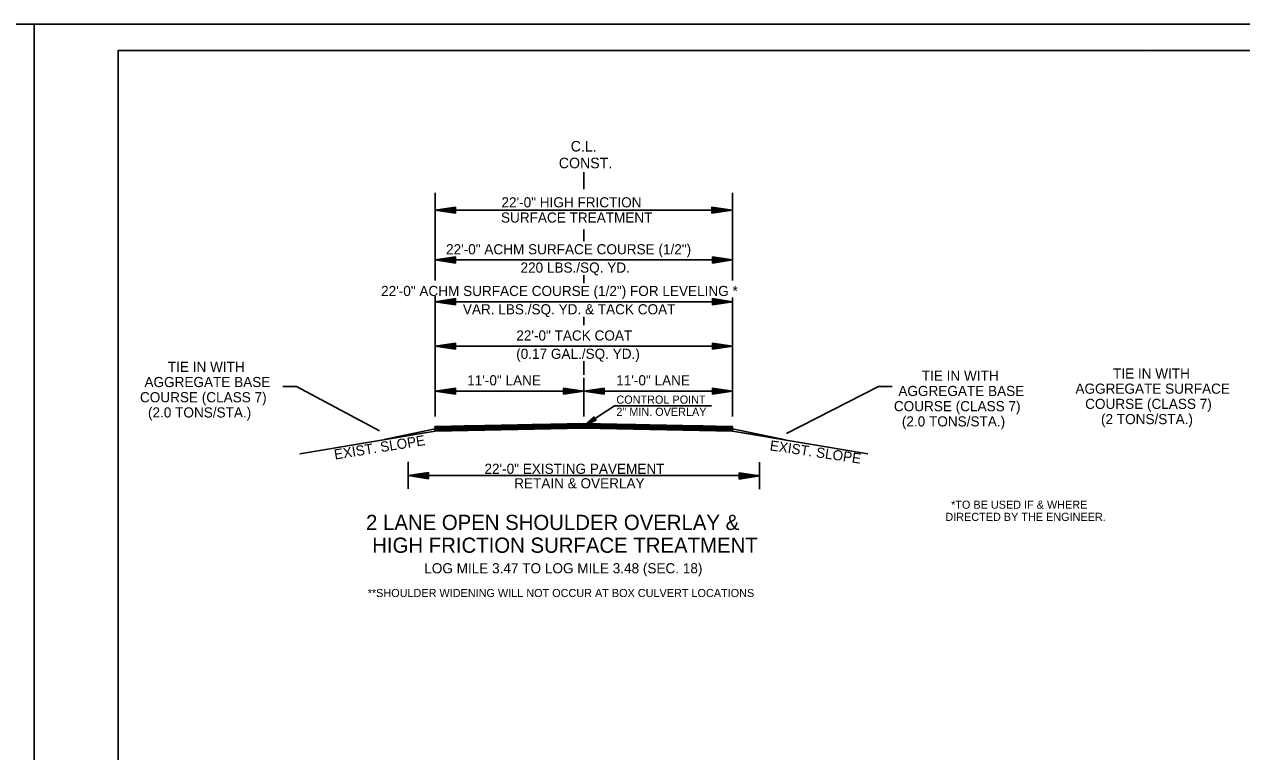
# Model space of a CAD drawing. Extents: x 2263886 to 2266026, y -3122850 to -3121850.
# Drawn here: x 2265358.3 to 2265448.3, y -3122391 to -3122337.2 of the extents above; entities that cross this region are included whole.
import ezdxf

# ---------------------------------------------------------------- set-up
doc = ezdxf.new("R2010")
doc.units = 0
for name, color, linetype in [('_CIVIL_CONSTRUCTION', 7, 'Continuous'), ('R_Border Notes', 7, 'Continuous'), ('R_Border Prem', 7, 'Continuous'), ('R_Draft', 7, 'Continuous')]:
    doc.layers.add(name, color=color, linetype=linetype)

msp = doc.modelspace()

# ---------------------------------------------------------------- linework, layer by layer
at = {"layer": '_CIVIL_CONSTRUCTION'}
for p, q in [((2265192.355, -3122337.151), (2265359.022, -3122337.151)), ((2265359.025, -3122337.151), (2265525.692, -3122337.151))]:
    msp.add_line(p, q, dxfattribs=at)
for points in [[(2265192.352, -3122337.151), (2265359.022, -3122337.151), (2265359.022, -3122443.82), (2265192.352, -3122443.82)], [(2265359.022, -3122337.151), (2265525.692, -3122337.151), (2265525.692, -3122443.82), (2265359.022, -3122443.82)], [(2265482.186, -3122339.098), (2265482.186, -3122344.038), (2265500.052, -3122344.038), (2265500.052, -3122345.498), (2265511.651, -3122345.498), (2265511.651, -3122357.664), (2265523.316, -3122357.664), (2265523.316, -3122441.828), (2265365.226, -3122441.828), (2265365.226, -3122339.098)]]:
    msp.add_lwpolyline(points, close=True, dxfattribs=at)
at = {"layer": 'R_Border Notes'}
for p, q in [((2265388.659, -3122366.913), (2265399.654, -3122366.693)), ((2265388.659, -3122366.913), (2265388.663, -3122367.083)), ((2265399.329, -3122366.87), (2265390.83, -3122366.87)), ((2265399.762, -3122366.77), (2265395.828, -3122366.77)), ((2265399.654, -3122366.693), (2265410.652, -3122366.913)), ((2265403.479, -3122366.77), (2265399.861, -3122366.77)), ((2265408.478, -3122366.87), (2265399.985, -3122366.87)), ((2265410.652, -3122366.913), (2265410.655, -3122367.083)), ((2265394.33, -3122366.97), (2265388.659, -3122366.97)), ((2265389.332, -3122367.07), (2265388.659, -3122367.07)), ((2265410.653, -3122366.97), (2265404.984, -3122366.97)), ((2265410.655, -3122367.07), (2265409.983, -3122367.07))]:
    msp.add_line(p, q, dxfattribs=at)
at = {"layer": 'R_Border Prem'}
for p, q in [((2265399.669, -3122349.342), (2265399.669, -3122348.088)), ((2265388.669, -3122356.108), (2265388.669, -3122349.609)), ((2265410.669, -3122356.108), (2265410.669, -3122349.609)), ((2265390.169, -3122350.669), (2265388.669, -3122350.894)), ((2265390.169, -3122350.707), (2265388.919, -3122350.894)), ((2265390.169, -3122351.119), (2265390.169, -3122350.669)), ((2265409.133, -3122350.669), (2265410.633, -3122350.894)), ((2265409.133, -3122350.669), (2265409.133, -3122351.119)), ((2265409.133, -3122350.707), (2265410.383, -3122350.894)), ((2265388.669, -3122350.894), (2265410.633, -3122350.894)), ((2265390.169, -3122351.119), (2265388.669, -3122350.894)), ((2265390.169, -3122351.082), (2265388.919, -3122350.894)), ((2265390.169, -3122350.745), (2265389.177, -3122350.894)), ((2265390.169, -3122351.044), (2265389.177, -3122350.894)), ((2265390.169, -3122350.783), (2265389.427, -3122350.894)), ((2265390.169, -3122351.006), (2265389.427, -3122350.894)), ((2265390.169, -3122350.821), (2265389.681, -3122350.894)), ((2265390.169, -3122350.967), (2265389.681, -3122350.894)), ((2265390.169, -3122350.859), (2265389.932, -3122350.894)), ((2265390.169, -3122350.93), (2265389.932, -3122350.894)), ((2265409.133, -3122350.745), (2265410.125, -3122350.894)), ((2265409.133, -3122350.783), (2265409.875, -3122350.894)), ((2265409.133, -3122350.822), (2265409.621, -3122350.894)), ((2265409.133, -3122350.859), (2265409.37, -3122350.894)), ((2265409.133, -3122351.119), (2265410.633, -3122350.894)), ((2265409.133, -3122350.968), (2265409.621, -3122350.894)), ((2265409.133, -3122351.044), (2265410.125, -3122350.894)), ((2265409.133, -3122351.082), (2265410.383, -3122350.894)), ((2265409.133, -3122351.006), (2265409.875, -3122350.894)), ((2265409.133, -3122350.93), (2265409.37, -3122350.894)), ((2265399.669, -3122353.204), (2265399.669, -3122352.332)), ((2265390.169, -3122354.362), (2265388.669, -3122354.587)), ((2265390.169, -3122354.812), (2265388.669, -3122354.587)), ((2265388.669, -3122354.587), (2265410.669, -3122354.587)), ((2265390.169, -3122354.399), (2265388.919, -3122354.587)), ((2265390.169, -3122354.774), (2265388.919, -3122354.587)), ((2265390.169, -3122354.437), (2265389.177, -3122354.587)), ((2265390.169, -3122354.736), (2265389.177, -3122354.587)), ((2265390.169, -3122354.475), (2265389.427, -3122354.587)), ((2265390.169, -3122354.698), (2265389.427, -3122354.587)), ((2265390.169, -3122354.513), (2265389.681, -3122354.587)), ((2265390.169, -3122354.659), (2265389.681, -3122354.587)), ((2265390.169, -3122354.551), (2265389.932, -3122354.587)), ((2265390.169, -3122354.622), (2265389.932, -3122354.587)), ((2265390.169, -3122354.812), (2265390.169, -3122354.362)), ((2265409.169, -3122354.362), (2265410.669, -3122354.587)), ((2265409.169, -3122354.362), (2265409.169, -3122354.812)), ((2265409.169, -3122354.399), (2265410.418, -3122354.587)), ((2265409.169, -3122354.437), (2265410.16, -3122354.587)), ((2265409.169, -3122354.475), (2265409.91, -3122354.587)), ((2265409.169, -3122354.514), (2265409.656, -3122354.587)), ((2265409.169, -3122354.551), (2265409.406, -3122354.587)), ((2265409.169, -3122354.812), (2265410.669, -3122354.587)), ((2265409.169, -3122354.66), (2265409.656, -3122354.587)), ((2265409.169, -3122354.736), (2265410.16, -3122354.587)), ((2265409.169, -3122354.774), (2265410.418, -3122354.587)), ((2265409.169, -3122354.698), (2265409.91, -3122354.587)), ((2265409.169, -3122354.622), (2265409.406, -3122354.587)), ((2265399.669, -3122356.299), (2265399.669, -3122355.717)), ((2265388.669, -3122366.166), (2265388.669, -3122357.257)), ((2265390.169, -3122357.449), (2265388.669, -3122357.674)), ((2265390.169, -3122357.899), (2265388.669, -3122357.674)), ((2265388.669, -3122357.674), (2265410.669, -3122357.674)), ((2265390.169, -3122357.486), (2265388.919, -3122357.674)), ((2265390.169, -3122357.861), (2265388.919, -3122357.674)), ((2265390.169, -3122357.524), (2265389.177, -3122357.674)), ((2265390.169, -3122357.823), (2265389.177, -3122357.674)), ((2265390.169, -3122357.562), (2265389.427, -3122357.674)), ((2265390.169, -3122357.785), (2265389.427, -3122357.674)), ((2265390.169, -3122357.6), (2265389.681, -3122357.674)), ((2265390.169, -3122357.746), (2265389.681, -3122357.674)), ((2265390.169, -3122357.638), (2265389.932, -3122357.674)), ((2265390.169, -3122357.709), (2265389.932, -3122357.674)), ((2265390.169, -3122357.899), (2265390.169, -3122357.449)), ((2265409.169, -3122357.449), (2265410.669, -3122357.674)), ((2265409.169, -3122357.449), (2265409.169, -3122357.899)), ((2265409.169, -3122357.486), (2265410.418, -3122357.674)), ((2265409.169, -3122357.524), (2265410.16, -3122357.674)), ((2265409.169, -3122357.562), (2265409.91, -3122357.674)), ((2265409.169, -3122357.601), (2265409.656, -3122357.674)), ((2265409.169, -3122357.638), (2265409.406, -3122357.674)), ((2265409.169, -3122357.899), (2265410.669, -3122357.674)), ((2265409.169, -3122357.747), (2265409.656, -3122357.674)), ((2265409.169, -3122357.823), (2265410.16, -3122357.674)), ((2265409.169, -3122357.861), (2265410.418, -3122357.674)), ((2265409.169, -3122357.785), (2265409.91, -3122357.674)), ((2265409.169, -3122357.709), (2265409.406, -3122357.674)), ((2265410.669, -3122366.166), (2265410.669, -3122357.358)), ((2265399.669, -3122359.412), (2265399.669, -3122358.803)), ((2265390.169, -3122360.742), (2265388.669, -3122360.967)), ((2265390.169, -3122361.192), (2265388.669, -3122360.967)), ((2265388.669, -3122360.967), (2265410.669, -3122360.967)), ((2265390.169, -3122360.779), (2265388.919, -3122360.967)), ((2265390.169, -3122361.154), (2265388.919, -3122360.967)), ((2265390.169, -3122360.817), (2265389.177, -3122360.967)), ((2265390.169, -3122361.116), (2265389.177, -3122360.967)), ((2265390.169, -3122360.855), (2265389.427, -3122360.967)), ((2265390.169, -3122361.078), (2265389.427, -3122360.967)), ((2265390.169, -3122360.893), (2265389.681, -3122360.967)), ((2265390.169, -3122361.039), (2265389.681, -3122360.967)), ((2265390.169, -3122360.931), (2265389.932, -3122360.967)), ((2265390.169, -3122361.002), (2265389.932, -3122360.967)), ((2265390.169, -3122361.192), (2265390.169, -3122360.742)), ((2265409.169, -3122360.742), (2265410.669, -3122360.967)), ((2265409.169, -3122360.742), (2265409.169, -3122361.192)), ((2265409.169, -3122360.779), (2265410.418, -3122360.967)), ((2265409.169, -3122360.817), (2265410.16, -3122360.967)), ((2265409.169, -3122360.855), (2265409.91, -3122360.967)), ((2265409.169, -3122360.894), (2265409.656, -3122360.967)), ((2265409.169, -3122360.931), (2265409.406, -3122360.967)), ((2265409.169, -3122361.192), (2265410.669, -3122360.967)), ((2265409.169, -3122361.04), (2265409.656, -3122360.967)), ((2265409.169, -3122361.116), (2265410.16, -3122360.967)), ((2265409.169, -3122361.154), (2265410.418, -3122360.967)), ((2265409.169, -3122361.078), (2265409.91, -3122360.967)), ((2265409.169, -3122361.002), (2265409.406, -3122360.967)), ((2265399.669, -3122363.098), (2265399.669, -3122362.081)), ((2265399.669, -3122366.166), (2265399.669, -3122363.31)), ((2265390.169, -3122364.075), (2265388.669, -3122364.3)), ((2265390.169, -3122364.112), (2265388.919, -3122364.3)), ((2265390.169, -3122364.15), (2265389.177, -3122364.3)), ((2265390.169, -3122364.188), (2265389.427, -3122364.3)), ((2265390.169, -3122364.226), (2265389.681, -3122364.3)), ((2265390.169, -3122364.525), (2265390.169, -3122364.075)), ((2265398.169, -3122364.075), (2265399.669, -3122364.3)), ((2265398.169, -3122364.075), (2265398.169, -3122364.525)), ((2265398.169, -3122364.112), (2265399.418, -3122364.3)), ((2265398.169, -3122364.15), (2265399.16, -3122364.3)), ((2265398.169, -3122364.188), (2265398.91, -3122364.3)), ((2265398.169, -3122364.227), (2265398.656, -3122364.3)), ((2265401.169, -3122364.075), (2265399.669, -3122364.3)), ((2265401.169, -3122364.112), (2265399.919, -3122364.3)), ((2265401.169, -3122364.15), (2265400.177, -3122364.3)), ((2265401.169, -3122364.188), (2265400.427, -3122364.3)), ((2265401.169, -3122364.226), (2265400.681, -3122364.3)), ((2265401.169, -3122364.525), (2265401.169, -3122364.075)), ((2265409.169, -3122364.075), (2265410.669, -3122364.3)), ((2265409.169, -3122364.075), (2265409.169, -3122364.525)), ((2265409.169, -3122364.112), (2265410.418, -3122364.3)), ((2265409.169, -3122364.15), (2265410.16, -3122364.3)), ((2265409.169, -3122364.188), (2265409.91, -3122364.3)), ((2265409.169, -3122364.227), (2265409.656, -3122364.3)), ((2265390.169, -3122364.525), (2265388.669, -3122364.3)), ((2265388.669, -3122364.3), (2265399.669, -3122364.3)), ((2265390.169, -3122364.487), (2265388.919, -3122364.3)), ((2265390.169, -3122364.449), (2265389.177, -3122364.3)), ((2265390.169, -3122364.411), (2265389.427, -3122364.3)), ((2265390.169, -3122364.372), (2265389.681, -3122364.3)), ((2265390.169, -3122364.264), (2265389.932, -3122364.3)), ((2265390.169, -3122364.335), (2265389.932, -3122364.3)), ((2265398.169, -3122364.264), (2265398.406, -3122364.3)), ((2265398.169, -3122364.525), (2265399.669, -3122364.3)), ((2265398.169, -3122364.373), (2265398.656, -3122364.3)), ((2265398.169, -3122364.449), (2265399.16, -3122364.3)), ((2265398.169, -3122364.487), (2265399.418, -3122364.3)), ((2265398.169, -3122364.411), (2265398.91, -3122364.3)), ((2265398.169, -3122364.335), (2265398.406, -3122364.3)), ((2265401.169, -3122364.525), (2265399.669, -3122364.3)), ((2265399.669, -3122364.3), (2265410.669, -3122364.3)), ((2265401.169, -3122364.487), (2265399.919, -3122364.3)), ((2265401.169, -3122364.449), (2265400.177, -3122364.3)), ((2265401.169, -3122364.411), (2265400.427, -3122364.3)), ((2265401.169, -3122364.372), (2265400.681, -3122364.3)), ((2265401.169, -3122364.264), (2265400.932, -3122364.3)), ((2265401.169, -3122364.335), (2265400.932, -3122364.3)), ((2265409.169, -3122364.264), (2265409.406, -3122364.3)), ((2265409.169, -3122364.525), (2265410.669, -3122364.3)), ((2265409.169, -3122364.373), (2265409.656, -3122364.3)), ((2265409.169, -3122364.449), (2265410.16, -3122364.3)), ((2265409.169, -3122364.487), (2265410.418, -3122364.3)), ((2265409.169, -3122364.411), (2265409.91, -3122364.3)), ((2265409.169, -3122364.335), (2265409.406, -3122364.3)), ((2265399.657, -3122366.863), (2265401.94, -3122365.374)), ((2265401.94, -3122365.374), (2265409.117, -3122365.374)), ((2265388.659, -3122367.083), (2265399.657, -3122366.863)), ((2265402.403, -3122366.918), (2265396.911, -3122366.918)), ((2265399.904, -3122366.868), (2265399.411, -3122366.868)), ((2265400.412, -3122366.19), (2265399.657, -3122366.863)), ((2265400.576, -3122366.441), (2265399.657, -3122366.863)), ((2265399.657, -3122366.863), (2265410.655, -3122367.083)), ((2265400.426, -3122366.211), (2265399.797, -3122366.772)), ((2265400.562, -3122366.42), (2265399.797, -3122366.772)), ((2265400.439, -3122366.233), (2265399.941, -3122366.678)), ((2265400.548, -3122366.399), (2265399.941, -3122366.678)), ((2265400.453, -3122366.254), (2265400.08, -3122366.587)), ((2265400.535, -3122366.378), (2265400.08, -3122366.587)), ((2265400.467, -3122366.275), (2265400.222, -3122366.494)), ((2265400.521, -3122366.356), (2265400.222, -3122366.494)), ((2265400.481, -3122366.296), (2265400.362, -3122366.402)), ((2265400.507, -3122366.336), (2265400.362, -3122366.402)), ((2265400.576, -3122366.441), (2265400.412, -3122366.19)), ((2265388.663, -3122367.253), (2265378.656, -3122368.921)), ((2265388.663, -3122367.083), (2265384.914, -3122367.878)), ((2265384.914, -3122367.878), (2265388.663, -3122367.253)), ((2265388.663, -3122367.253), (2265399.661, -3122367.033)), ((2265388.663, -3122367.253), (2265388.663, -3122367.083)), ((2265388.663, -3122367.253), (2265388.663, -3122367.083)), ((2265388.663, -3122367.254), (2265388.663, -3122367.083)), ((2265395.413, -3122367.118), (2265388.663, -3122367.118)), ((2265392.913, -3122367.168), (2265388.663, -3122367.168)), ((2265390.413, -3122367.218), (2265388.663, -3122367.218)), ((2265388.663, -3122367.253), (2265388.663, -3122367.253)), ((2265397.912, -3122367.068), (2265389.413, -3122367.068)), ((2265407.402, -3122367.018), (2265391.912, -3122367.018)), ((2265404.903, -3122366.968), (2265394.412, -3122366.968)), ((2265399.654, -3122367.033), (2265410.652, -3122367.253)), ((2265409.902, -3122367.068), (2265401.408, -3122367.068)), ((2265410.655, -3122367.118), (2265403.905, -3122367.118)), ((2265410.655, -3122367.168), (2265406.403, -3122367.168)), ((2265410.655, -3122367.218), (2265408.901, -3122367.218)), ((2265410.649, -3122367.238), (2265410.276, -3122367.238)), ((2265410.655, -3122367.083), (2265410.655, -3122367.253)), ((2265414.579, -3122367.907), (2265410.655, -3122367.083)), ((2265420.662, -3122368.921), (2265410.655, -3122367.253)), ((2265410.655, -3122367.253), (2265410.655, -3122367.253)), ((2265410.655, -3122367.253), (2265414.579, -3122367.907)), ((2265386.669, -3122369.522), (2265386.669, -3122371.522)), ((2265412.653, -3122369.547), (2265412.653, -3122371.547)), ((2265388.169, -3122370.322), (2265386.669, -3122370.547)), ((2265388.169, -3122370.359), (2265386.919, -3122370.547)), ((2265388.169, -3122370.397), (2265387.177, -3122370.547)), ((2265388.169, -3122370.435), (2265387.427, -3122370.547)), ((2265388.169, -3122370.473), (2265387.681, -3122370.547)), ((2265388.169, -3122370.511), (2265387.932, -3122370.547)), ((2265388.169, -3122370.772), (2265388.169, -3122370.322)), ((2265411.153, -3122370.347), (2265412.653, -3122370.572)), ((2265411.153, -3122370.347), (2265411.153, -3122370.797)), ((2265411.153, -3122370.384), (2265412.402, -3122370.572)), ((2265411.153, -3122370.422), (2265412.144, -3122370.572)), ((2265411.153, -3122370.46), (2265411.894, -3122370.572)), ((2265411.153, -3122370.499), (2265411.64, -3122370.572)), ((2265411.153, -3122370.536), (2265411.39, -3122370.572)), ((2265388.169, -3122370.772), (2265386.669, -3122370.547)), ((2265386.669, -3122370.547), (2265412.653, -3122370.547)), ((2265388.169, -3122370.734), (2265386.919, -3122370.547)), ((2265388.169, -3122370.696), (2265387.177, -3122370.547)), ((2265388.169, -3122370.658), (2265387.427, -3122370.547)), ((2265388.169, -3122370.619), (2265387.681, -3122370.547)), ((2265388.169, -3122370.582), (2265387.932, -3122370.547)), ((2265411.153, -3122370.797), (2265412.653, -3122370.572)), ((2265411.153, -3122370.645), (2265411.64, -3122370.572)), ((2265411.153, -3122370.721), (2265412.144, -3122370.572)), ((2265411.153, -3122370.759), (2265412.402, -3122370.572)), ((2265411.153, -3122370.683), (2265411.894, -3122370.572)), ((2265411.153, -3122370.607), (2265411.39, -3122370.572))]:
    msp.add_line(p, q, dxfattribs=at)
for points in [[(2265377.418, -3122363.941), (2265378.418, -3122363.941), (2265384.566, -3122367.231)], [(2265422.457, -3122363.941), (2265421.457, -3122363.941), (2265414.646, -3122367.428)]]:
    msp.add_lwpolyline(points, dxfattribs=at)
at = {"layer": 'R_Draft'}
for p, q in [((2265365.226, -3122339.098), (2265523.316, -3122339.098)), ((2265365.226, -3122441.828), (2265365.226, -3122339.098)), ((2265441.486, -3122339.228), (2265441.486, -3122339.228)), ((2265441.486, -3122339.228), (2265441.486, -3122339.228))]:
    msp.add_line(p, q, dxfattribs=at)

# ---------------------------------------------------------------- texts
at = {"layer": 'R_Border Prem'}
for s, height, p in [('C.L.', 0.78, (2265398.697, -3122346.563)), ('CONST.', 0.78, (2265397.819, -3122347.8)), ('22\'-0" HIGH FRICTION', 0.75, (2265393.575, -3122350.697)), ('SURFACE TREATMENT', 0.75, (2265393.54, -3122351.822)), ('22\'-0" ACHM SURFACE COURSE (1/2")', 0.75, (2265389.477, -3122354.17)), ('220 LBS./SQ. YD. ', 0.75, (2265394.984, -3122355.524)), ('22\'-0" ACHM SURFACE COURSE (1/2") FOR LEVELING *', 0.75, (2265384.676, -3122357.257)), ('VAR. LBS./SQ. YD. & TACK COAT', 0.75, (2265390.723, -3122358.611)), ('22\'-0" TACK COAT', 0.75, (2265394.671, -3122360.55)), ('(0.17 GAL./SQ. YD.)', 0.75, (2265394.665, -3122361.904)), ('TIE IN WITH ', 0.75, (2265368.91, -3122362.869)), ('AGGREGATE BASE', 0.75, (2265367.18, -3122363.994)), ('11\'-0" LANE', 0.75, (2265391.042, -3122363.867)), ('11\'-0" LANE', 0.75, (2265402.06, -3122363.867)), ('TIE IN WITH ', 0.75, (2265424.651, -3122363.531)), ('TIE IN WITH ', 0.75, (2265438.794, -3122363.361)), ('AGGREGATE BASE', 0.75, (2265422.921, -3122364.656)), ('AGGREGATE SURFACE', 0.75, (2265436.013, -3122364.486)), ('COURSE (CLASS 7)', 0.75, (2265366.849, -3122365.119)), ('CONTROL POINT', 0.6, (2265402.073, -3122365.221)), ('COURSE (CLASS 7)', 0.75, (2265422.59, -3122365.781)), ('COURSE (CLASS 7)', 0.75, (2265436.733, -3122365.611)), ('(2.0 TONS/STA.)', 0.75, (2265367.44, -3122366.244)), ('2" MIN. OVERLAY', 0.6, (2265402.073, -3122366.121)), ('(2 TONS/STA.)', 0.75, (2265437.903, -3122366.736)), ('(2.0 TONS/STA.)', 0.75, (2265423.181, -3122366.906)), ('22\'-0" EXISTING PAVEMENT', 0.75, (2265392.318, -3122370.414)), ('RETAIN & OVERLAY', 0.75, (2265394.517, -3122371.487)), ('*TO BE USED IF & WHERE', 0.6, (2265426.82, -3122372.995)), ('2 LANE OPEN SHOULDER OVERLAY &', 1.125, (2265383.564, -3122374.568)), ('DIRECTED BY THE ENGINEER.', 0.6, (2265426.395, -3122373.895)), ('HIGH FRICTION SURFACE TREATMENT', 1.125, (2265384.021, -3122376.256)), ('LOG MILE 3.47 TO LOG MILE 3.48 (SEC. 18)', 0.75, (2265387.867, -3122377.775)), ('**SHOULDER WIDENING WILL NOT OCCUR AT BOX CULVERT LOCATIONS', 0.6, (2265383.686, -3122379.531))]:
    msp.add_text(s, height=height, dxfattribs=at).set_placement(p)
for rotation, p in [(9.15344, (2265381.265, -3122369.362)), (351.57554, (2265413.379, -3122368.669))]:
    msp.add_text('EXIST. SLOPE', height=0.75, rotation=rotation, dxfattribs=at).set_placement(p)

doc.saveas('drawing.dxf')
